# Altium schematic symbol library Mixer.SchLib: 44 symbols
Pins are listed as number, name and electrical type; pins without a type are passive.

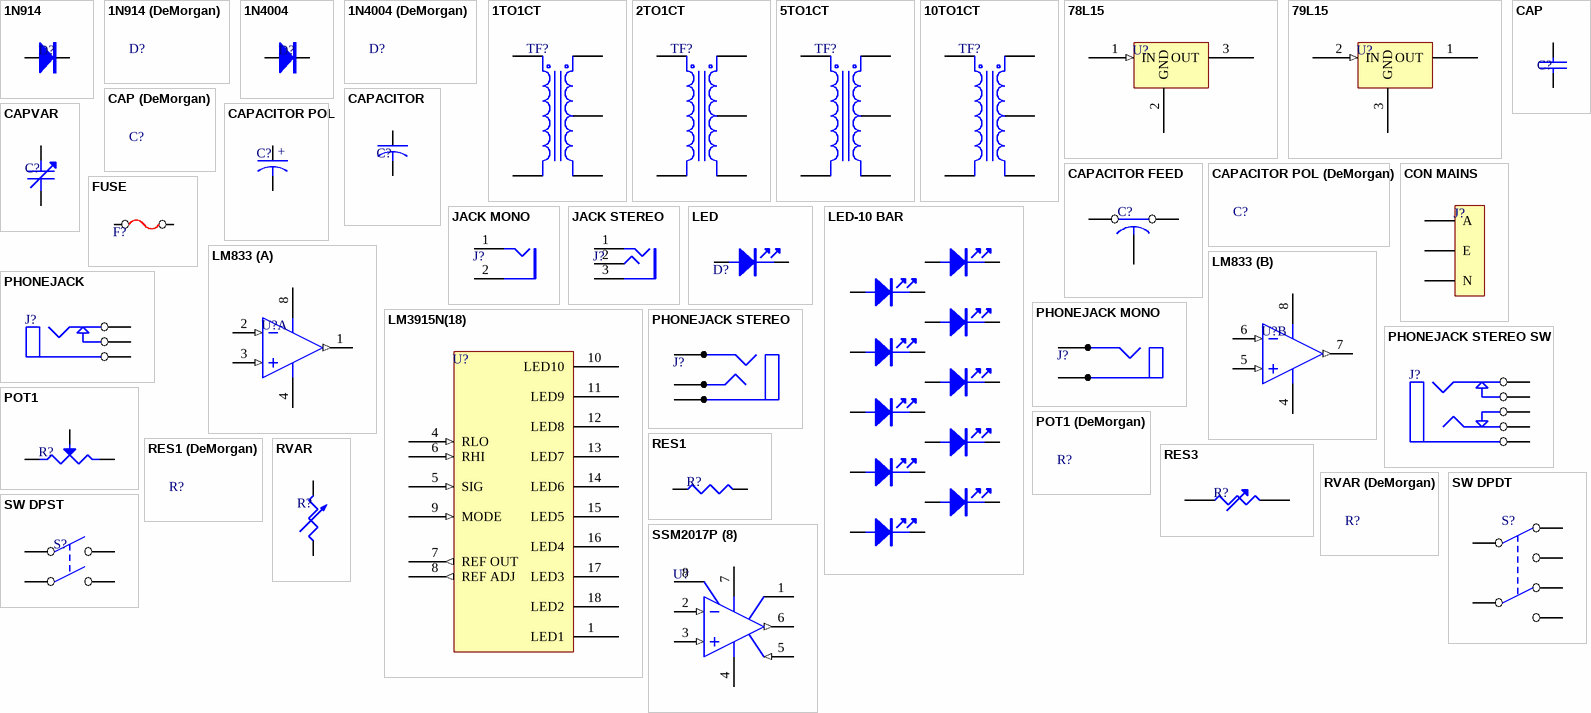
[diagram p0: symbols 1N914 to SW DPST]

## 1N914
designator D?
Diode
footprint DIODE0.4
footprint DIODE0.5
simulation model 1N914 (DIODE)
pins: 1 A, 2 K

## 1N914 (DeMorgan)
designator D?
Diode
footprint DIODE0.4
footprint DIODE0.5
simulation model 1N914 (DeMorgan) (DIODE)

## 1N4004
designator D?
Diode
footprint DIODE0.5
simulation model 1N4004 (DIODE)
pins: 1 A, 2 K

## 1N4004 (DeMorgan)
designator D?
Diode
footprint DIODE0.5
simulation model 1N4004 (DeMorgan) (DIODE)

## 1TO1CT
designator TF?
Center-Tapped Transformer
footprint TRANSFORMER
simulation model 1TO1CT (SUBCKT)
pins: 1 Pri+, 2 Pri-, 3 Sec+, 4 SecCT, 5 Sec-

## 2TO1CT
designator TF?
Center-Tapped Transformer
footprint TRANSFORMER
simulation model 2TO1CT (SUBCKT)
pins: 1 Pri+, 2 Pri-, 3 Sec+, 4 SecCT, 5 Sec-

## 5TO1CT
designator TF?
Center-Tapped Transformer
footprint TRANSFORMER
simulation model 5TO1CT (SUBCKT)
pins: 1 Pri+, 2 Pri-, 3 Sec+, 4 SecCT, 5 Sec-

## 10TO1CT
designator TF?
Center-Tapped Transformer
footprint TRANSFORMER
simulation model 10TO1CT (SUBCKT)
pins: 1 Pri+, 2 Pri-, 3 Sec+, 4 SecCT, 5 Sec-

## 78L15
designator U?
Very Low Drop Voltage Regulators With Inhibit
footprint TO-92A
footprint TO-220
pins: 1 IN (in), 2 GND (power), 3 OUT (power)

## 79L15
designator U?
Very Low Drop Voltage Regulators With Inhibit
footprint TO-92A
footprint TO-220
pins: 1 OUT (power), 2 IN (in), 3 GND (power)

## CAP
designator C?
Capacitor
footprint RAD0.2
footprint RAD0.8
footprint RB.2/.4-NP
simulation model CAP
pins: 1, 2

## CAP (DeMorgan)
designator C?
Capacitor
footprint RAD0.2
footprint RAD0.8
footprint RB.2/.4-NP
simulation model CAP

## CAPACITOR
designator C?
Capacitor
pins: 1, 2

## CAPACITOR FEED
designator C?
Feed-Through Capacitor
pins: 1, 2, 3

## CAPACITOR POL
designator C?
Bi-Polar Capacitor
footprint RB.2/.4
footprint RB.4/.8
simulation model CAP
pins: 1, 2

## CAPACITOR POL (DeMorgan)
designator C?
Bi-Polar Capacitor
footprint RB.2/.4
footprint RB.4/.8
simulation model CAP

## CAPVAR
designator C?
Variable Capacitor
pins: 1, 2

## CON MAINS
designator J?
Connector
footprint IEC-MAINS
pins: 1 A, 2 E, 3 N

## FUSE
designator F?
Fuse
footprint FUSE
simulation model FUSE (SUBCKT)
pins: 1, 2

## JACK MONO
designator J?
XLR connector, PCB mounted
footprint XLR-FEMALE
pins: 1, 2

## JACK STEREO
designator J?
XLR connector, PCB mounted
footprint XLR-FEMALE
pins: 1, 2, 3

## LED
designator D?
pins: A 1, K 2

## LED-10 BAR
designator ?
footprint LED - 10 BAR HORIZONTAL
pins: 1 A, 2 K, 3 A, 4 K, 5 A, 6 K, 7 A, 8 K, 9 A, 10 K, 11 A, 12 K, 13 A, 14 K, 15 A, 16 K, 17 A, 18 K, 19 A, 20 K

## LM833
designator U?
Fast Settling Dual Operational Amplifier
footprint DIP8
simulation model LM833 (SUBCKT)
pins on every part: 4 V- (power), 8 V+ (power)
part A pins: 1 OUT1 (out), 2 IN1- (in), 3 IN1+ (in)
part B pins: 5 IN2+ (in), 6 IN2- (in), 7 OUT2 (out)

## LM3915N(18)
designator U?
Dot/Bar Display Driver
footprint DIP18
pins: 1 LED1 (oc), 2 V- (power) hidden, 3 V+ (power) hidden, 4 RLO (in), 5 SIG (in), 6 RHI (in), 7 REF OUT (out), 8 REF ADJ (out), 9 MODE (in), 10 LED10 (oc), 11 LED9 (oc), 12 LED8 (oc), 13 LED7 (oc), 14 LED6 (oc), 15 LED5 (oc), 16 LED4 (oc), 17 LED3 (oc), 18 LED2 (oc)

## PHONEJACK
designator J?
pins: 1 A, 2 B, 3 C

## PHONEJACK MONO
designator J?
footprint JACK-6.25MM
pins: 1 A, 3 C

## PHONEJACK STEREO
designator J?
footprint JACK-6.25MM
pins: 1 A, 2 B, 3 C

## PHONEJACK STEREO SW
designator J?
pins: 1 A, 2 B, 3 C, 4 D, 5 E

## POT1
designator R?
Potentiometer
footprint POT - 24MM
simulation model POT
pins: 1, 2 W, 3

## POT1 (DeMorgan)
designator R?
Potentiometer
footprint POT - 24MM
simulation model POT

## RES1
designator R?
Resistor
footprint AXIAL0.4
simulation model RESISTOR
pins: 1, 2

## RES1 (DeMorgan)
designator R?
Resistor
footprint AXIAL0.4
simulation model RESISTOR

## RES3
designator R?
pins: 1, 2

## RVAR
designator R?
Variable Resistor
simulation model VRES
pins: 1 TOP, 2 BOT

## RVAR (DeMorgan)
designator R?
Variable Resistor
simulation model VRES

## SSM2017P (8)
designator U?
Self-Contained Audio Preamplifier
footprint DIP8
pins: 1 RG1, 2 IN- (in), 3 IN+ (in), 4 V- (power), 5 REF (in), 6 OUT (out), 7 V+ (power), 8 RG2

## SW DPDT
designator S?
pins: 1 COMMON1, 2 NC1, 3 NO1, 4 NC2, 5 COMMON2, 6 NO2

## SW DPST
designator S?
pins: 1 COMMON1, 2 NO1, 3 COMMON2, 4 NO2

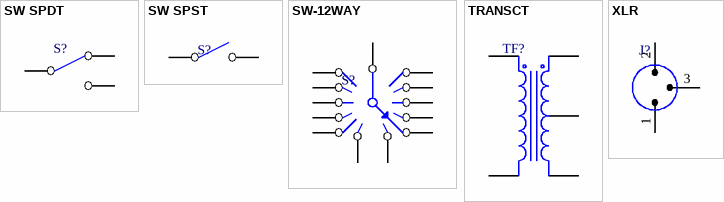
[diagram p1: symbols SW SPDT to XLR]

## SW SPDT
designator S?
footprint SW-SPDT
pins: 1 COMMON, 2 NC, 3 NO

## SW SPST
designator S?
pins: 1 COMMON, 2 NO

## SW-12WAY
designator S?
footprint SW-12WAY
pins: 1, 2, 3, 4, 5, 6, 7, 8, 9, 10, 11, 12, 13

## TRANSCT
designator TF?
Center-Tapped Transformer
footprint TRANSFORMER
simulation model TRANSCT (SUBCKT)
pins: 1 Pri+, 2 Pri-, 3 Sec+, 4 SecCT, 5 Sec-

## XLR
designator J?
XLR connector, PCB mounted
footprint XLR-FEMALE
footprint XLR-MALE
pins: 1, 2, 3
